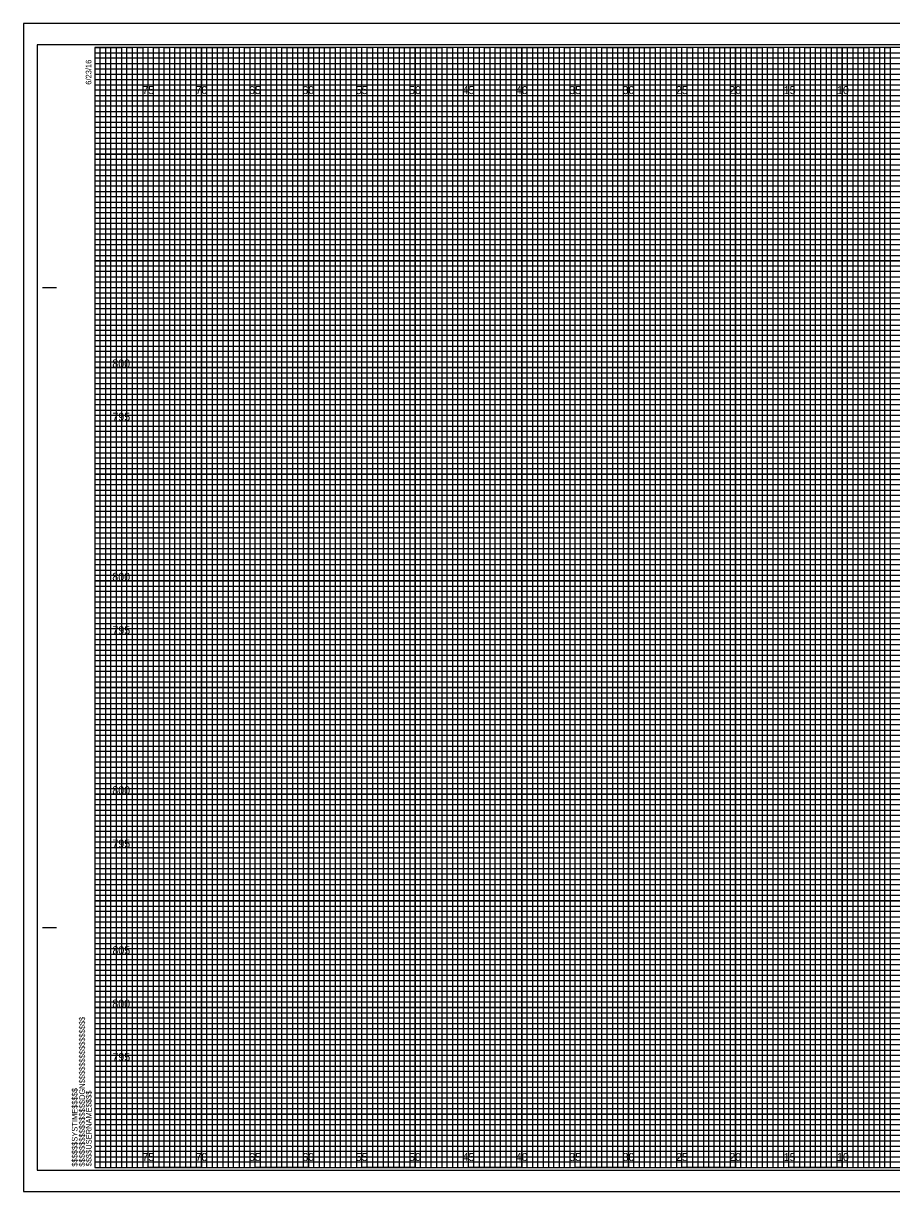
# Model space of a CAD drawing. Extents: x -7 to 162, y -2 to 107.
# Drawn here: x -6.7 to 74.6, y -2.3 to 107.3 of the extents above; entities that cross this region are included whole.
import ezdxf

# ---------------------------------------------------------------- set-up
doc = ezdxf.new("R2010")
doc.units = 0
for name, color, linetype in [('Exist CMT Pavement', 7, 'Continuous'), ('Exist Cross Section Cell', 7, 'Continuous'), ('Exist XS Center Line Elevation Label', 7, 'Continuous'), ('Prop CMT Concrete Structures', 7, 'Continuous'), ('Prop CMT Pvmt Course 2 Wedge', 7, 'Continuous'), ('Prop XS SE Text', 7, 'Continuous'), ('Prop XS Side Slope Text', 7, 'Continuous'), ('Sheet Cross Section Grid Minor 2 CELL', 7, 'Continuous'), ('Sheet DOT Grid CELL', 7, 'Continuous'), ('Sheet Plot Border Inside CELL', 7, 'Continuous'), ('Sheet Plot Border Outside CELL', 7, 'Continuous')]:
    doc.layers.add(name, color=color, linetype=linetype)

msp = doc.modelspace()

# ---------------------------------------------------------------- linework, layer by layer
at = {"layer": 'Exist Cross Section Cell'}
for p, q in [((5, 105), (0, 105)), ((5, 0), (5, 105)), ((15, 105), (10, 105)), ((10, 105), (10, 0)), ((15, 0), (15, 105)), ((25, 105), (20, 105)), ((20, 105), (20, 0)), ((25, 0), (25, 105)), ((35, 105), (30, 105)), ((30, 105), (30, 0)), ((35, 0), (35, 105)), ((45, 105), (40, 105)), ((40, 105), (40, 0)), ((45, 0), (45, 105)), ((55, 105), (50, 105)), ((50, 105), (50, 0)), ((55, 0), (55, 105)), ((65, 105), (60, 105)), ((60, 105), (60, 0)), ((65, 0), (65, 105)), ((75, 105), (70, 105)), ((70, 105), (70, 0)), ((10, 0), (5, 0)), ((20, 0), (15, 0)), ((30, 0), (25, 0)), ((40, 0), (35, 0)), ((50, 0), (45, 0)), ((60, 0), (55, 0)), ((70, 0), (65, 0))]:
    msp.add_line(p, q, dxfattribs=at)
for points in [[(0, 100), (160, 100), (160, 95), (0, 95)], [(0, 90), (160, 90), (160, 85), (0, 85)], [(0, 80), (160, 80), (160, 75), (0, 75)], [(0, 70), (160, 70), (160, 65), (0, 65)], [(0, 60), (160, 60), (160, 55), (0, 55)], [(0, 50), (160, 50), (160, 45), (0, 45)], [(0, 40), (160, 40), (160, 35), (0, 35)], [(0, 30), (160, 30), (160, 25), (0, 25)], [(0, 20), (160, 20), (160, 15), (0, 15)], [(0, 10), (160, 10), (160, 5), (0, 5)]]:
    msp.add_lwpolyline(points, dxfattribs=at)
at = {"layer": 'Exist XS Center Line Elevation Label'}
for points in [[(0, 105), (2.5, 105), (2.5, 0), (7.5, 0), (7.5, 105), (12.5, 105), (12.5, 0), (17.5, 0), (17.5, 105), (22.5, 105), (22.5, 0), (27.5, 0), (27.5, 105), (32.5, 105), (32.5, 0), (37.5, 0), (37.5, 105), (42.5, 105), (42.5, 0), (47.5, 0), (47.5, 105), (52.5, 105), (52.5, 0), (57.5, 0), (57.5, 105), (62.5, 105), (62.5, 0), (67.5, 0), (67.5, 105), (72.5, 105), (72.5, 0), (77.5, 0)], [(0, 102.5), (137.5, 102.5)], [(0, 92.5), (160, 92.5), (160, 97.5), (0, 97.5)], [(0, 82.5), (160, 82.5), (160, 87.5), (0, 87.5)], [(0, 72.5), (160, 72.5), (160, 77.5), (0, 77.5)], [(0, 62.5), (160, 62.5), (160, 67.5), (0, 67.5)], [(0, 52.5), (160, 52.5), (160, 57.5), (0, 57.5)], [(0, 42.5), (160, 42.5), (160, 47.5), (0, 47.5)], [(0, 32.5), (160, 32.5), (160, 37.5), (0, 37.5)], [(0, 22.5), (160, 22.5), (160, 27.5), (0, 27.5)], [(0, 12.5), (160, 12.5), (160, 17.5), (0, 17.5)], [(0, 2.5), (160, 2.5), (160, 7.5), (0, 7.5)]]:
    msp.add_lwpolyline(points, dxfattribs=at)
at = {"layer": 'Prop CMT Concrete Structures'}
for p, q in [((161.65, 107.25), (-6.7, 107.25)), ((-6.7, 107.25), (-6.7, -2.25)), ((-6.7, -2.25), (161.65, -2.25))]:
    msp.add_line(p, q, dxfattribs=at)
at = {"layer": 'Prop CMT Pvmt Course 2 Wedge'}
for p, q in [((-4.9, 82.5), (-3.65, 82.5)), ((-4.85, 82.5), (-3.6, 82.5)), ((-4.9, 22.5), (-3.65, 22.5)), ((-4.85, 22.5), (-3.6, 22.5)), ((0, 0), (0, 0)), ((0, 0), (0, 0)), ((0, 0), (0, 0)), ((0, 0), (0, 0)), ((0, 0), (0, 0)), ((0, 0), (0, 0)), ((0, 0), (0, 0))]:
    msp.add_line(p, q, dxfattribs=at)
msp.add_lwpolyline([(160, 105), (0, 105), (0, 0), (160, 0)], close=True, dxfattribs=at)
at = {"layer": 'Prop XS Side Slope Text'}
for p, q in [((0, 104.5), (130, 104.5)), ((130, 103.99), (0, 103.99)), ((0, 103.99), (0, 103.5)), ((0, 103.5), (130, 103.5)), ((130, 102.95), (0, 102.95)), ((0, 102.95), (0, 102)), ((0, 102), (160, 102))]:
    msp.add_line(p, q, dxfattribs=at)
for points in [[(0, 101.5), (135, 101.5), (160, 101.5), (160, 101), (0, 101)], [(0, 100.5), (160, 100.5), (160, 99.5), (0, 99.5)], [(0, 99), (160, 99), (160, 98.5), (0, 98.49)], [(0, 98), (160, 98), (160, 97), (0, 97)], [(0, 96.5), (160, 96.5), (160, 96), (0, 96)], [(0, 95.5), (160, 95.5), (160, 94.5), (0, 94.5)], [(0, 94), (160, 94), (160, 93.5), (0, 93.5)], [(0, 93), (160, 93), (160, 92), (0, 92)], [(0, 91.5), (160, 91.5), (160, 91), (0, 91)], [(0, 90.5), (160, 90.5), (160, 89.5), (0, 89.5)], [(0, 89), (160, 89), (160, 88.5), (0, 88.5)], [(0, 88), (160, 88), (160, 86.98), (160, 86.5), (160, 86), (0, 86)], [(0, 87), (160, 87), (160, 86.5), (0, 86.5)], [(0, 85.5), (160, 85.5), (160, 84.5), (0, 84.52)], [(0, 84.52), (160, 84.5), (160, 84), (0, 84)], [(0, 83.5), (160, 83.5), (160, 83), (0, 83)], [(0, 82), (160, 82), (160, 81.5), (0, 81.5)], [(0, 81), (160, 81), (160, 80.5), (0, 80.5)], [(-0.04, 79.45), (160, 79.45), (160, 78.94), (-0.04, 78.94)], [(0, 78.5), (160, 78.5), (160, 78), (0, 78)], [(0, 77), (160, 77), (160, 76.5), (0, 76.5)], [(0, 76), (160, 76), (160, 75.5), (0, 75.5)], [(0, 74.5), (160, 74.5), (160, 74), (0, 74)], [(0, 73.5), (160, 73.5), (160, 73), (0, 73)], [(0, 72), (160, 72), (160, 71.5), (0, 71.5)], [(0, 71), (160, 71), (160, 70.5), (0, 70.5)], [(0, 69.5), (160, 69.5), (160, 68.99), (0, 69)], [(0, 68.5), (160, 68.5), (160, 68), (0, 68)], [(0, 67), (160, 67), (160, 66.5), (0, 66.5)], [(0, 66), (160, 66), (160, 65.5), (0, 65.5)], [(0, 64.5), (160, 64.5), (160, 64), (0, 64)], [(0, 63.5), (160, 63.5), (160, 63), (0, 63)], [(0, 62), (160, 62), (160, 61.5), (0, 61.5)], [(0, 61), (160, 61), (160, 60.5), (0, 60.5)], [(0, 59.5), (160, 59.5), (160, 59), (0, 59)], [(0, 58.5), (160.03, 58.45), (160, 58), (0, 58)], [(0, 57), (160, 57), (160, 56.5), (0, 56.5)], [(0, 56), (160, 56), (160, 55.5), (0, 55.5)], [(0, 54.5), (160, 54.5), (160, 54), (0, 54)], [(0, 53.5), (160, 53.5), (160, 53), (0, 53)], [(0, 52), (160, 52), (160, 51.5), (0, 51.5)], [(0, 51), (160, 51), (160, 50.5), (0, 50.5)], [(0, 49.5), (160, 49.5), (160, 49), (0, 49)], [(0, 48.5), (160, 48.5), (160, 48), (0, 48)], [(0, 47), (160, 47), (160, 46.5), (0, 46.5)], [(0, 46), (160, 46), (160, 45.5), (0, 45.5)], [(0, 44.5), (160, 44.5), (160, 44), (0, 44)], [(0, 43.5), (160, 43.5), (160, 43), (0, 43)], [(0, 42), (160, 42), (160, 41.5), (0, 41.5)], [(0, 41), (160, 41), (160, 40.5), (0, 40.5)], [(0, 39.5), (160, 39.5), (160, 38.99), (0, 39)], [(0, 38.5), (160, 38.5), (160, 38), (0, 38)], [(0, 37), (160, 37), (160, 36.5), (0, 36.5)], [(0, 36), (160, 36), (160, 35.5), (0, 35.5)], [(0, 34.5), (160, 34.5), (160, 34), (0, 34)], [(0, 33.5), (160, 33.5), (160, 33), (0, 33)], [(0, 32), (160, 32), (160, 31.5), (0, 31.5)], [(0, 31), (160, 31), (160, 30.5), (0, 30.5)], [(0, 29.5), (160, 29.5), (160, 29), (0, 29)], [(0, 28.5), (160.03, 28.46), (160, 28), (0, 28)], [(0, 27), (160, 27), (160, 26.5), (0, 26.5)], [(0, 26), (160, 26), (160, 25.5), (0, 25.5)], [(0, 24.5), (160, 24.5), (160, 24), (0, 24)], [(0, 23.5), (160, 23.5), (160, 23), (0, 23)], [(0, 22), (160, 22), (160, 21.5), (0, 21.5)], [(0, 21), (160, 21), (160, 20.5), (0, 20.5)], [(0, 19.5), (160, 19.5), (160, 19), (0, 19)], [(0, 18.5), (160, 18.5), (160, 18), (0, 18)], [(0, 17), (160, 17), (160, 16.5), (0, 16.5)], [(0, 16), (160, 16), (160, 15.5), (0, 15.5)], [(0, 14.5), (160, 14.5), (160, 14), (0, 14)], [(0, 13.5), (160, 13.5), (160, 13), (0, 13)], [(0, 12), (160, 12), (160, 11.5), (0, 11.5)], [(0, 11), (160, 11), (160, 10.5), (0, 10.5)], [(0, 9.5), (160, 9.5), (160, 9), (0, 9)], [(0, 8.5), (160, 8.5), (160, 8), (0, 8)], [(0, 7), (160, 7), (160, 6.5), (0, 6.5)], [(0, 6), (160, 6), (160, 5.5), (0, 5.5)], [(0, 4.5), (160, 4.5), (160, 4), (0, 4)], [(0, 3.5), (160, 3.5), (160, 3), (0, 3)], [(0, 2), (160, 2), (160, 1.5), (0, 1.5)], [(0, 1), (160, 1), (160, 0.5), (0, 0.5)]]:
    msp.add_lwpolyline(points, dxfattribs=at)
at = {"layer": 'Sheet Cross Section Grid Minor 2 CELL'}
for points in [[(0, 0), (0.5, 0), (0.5, 105), (1, 105), (1, 0)], [(1, 0), (1.5, 0), (1.5, 105), (2, 105), (2, 0)], [(2.5, 0), (3, 0), (3, 105), (3.5, 105), (3.5, 0)], [(3.5, 0), (4, 0), (4, 105), (4.5, 105), (4.5, 0)], [(5, 0), (5.5, 0), (5.5, 105), (6, 105), (6, 0)], [(6, 0), (6.5, 0), (6.5, 105), (7, 105), (7, 0)], [(7.5, 0), (8, 0), (8, 105), (8.5, 105), (8.5, 0)], [(8.5, 0), (9, 0), (9, 105), (9.5, 105), (9.5, 0)], [(10, 0), (10.5, 0), (10.5, 105), (11, 105), (11, 0)], [(11, 0), (11.5, 0), (11.5, 105), (12, 105), (12, 0)], [(12.5, 0), (13, 0), (13, 105), (13.5, 105), (13.5, 0)], [(13.5, 0), (14, 0), (14, 105), (14.5, 105), (14.5, 0)], [(15, 0), (15.5, 0), (15.5, 105), (16, 105), (16, 0)], [(16, 0), (16.5, 0), (16.5, 105), (17, 105), (17, 0)], [(17.5, 0), (18, 0), (18, 105), (18.5, 105), (18.5, 0)], [(18.5, 0), (19, 0), (19, 105), (19.5, 105), (19.5, 0)], [(20, 0), (20.5, 0), (20.5, 105), (21, 105), (21, 0)], [(21, 0), (21.5, 0), (21.5, 105), (22, 105), (22, 0)], [(22.5, 0), (23, 0), (23, 105), (23.5, 105), (23.5, 0)], [(23.5, 0), (24, 0), (24, 105), (24.5, 105), (24.5, 0)], [(25, 0), (25.5, 0), (25.5, 105), (26, 105), (26, 0)], [(26, 0), (26.5, 0), (26.5, 105), (27, 105), (27, 0)], [(27.5, 0), (28, 0), (28, 105), (28.5, 105), (28.5, 0)], [(28.5, 0), (29, 0), (29, 105), (29.5, 105), (29.5, 0)], [(30, 0), (30.5, 0), (30.5, 105), (31, 105), (31, 0)], [(31, 0), (31.5, 0), (31.5, 105), (32, 105), (32, 0)], [(32.5, 0), (33, 0), (33, 105), (33.5, 105), (33.5, 0)], [(33.5, 0), (34, 0), (34, 105), (34.5, 105), (34.5, 0)], [(35, 0), (35.5, 0), (35.5, 105), (36, 105), (36, 0)], [(36, 0), (36.5, 0), (36.5, 105), (37, 105), (37, 0)], [(37.5, 0), (38, 0), (38, 105), (38.5, 105), (38.5, 0)], [(38.5, 0), (39, 0), (39, 105), (39.5, 105), (39.5, 0)], [(40, 0), (40.5, 0), (40.5, 105), (41, 105), (41, 0)], [(41, 0), (41.5, 0), (41.5, 105), (42, 105), (42, 0)], [(42.5, 0), (43, 0), (43, 105), (43.5, 105), (43.5, 0)], [(43.5, 0), (44, 0), (44, 105), (44.5, 105), (44.5, 0)], [(45, 0), (45.5, 0), (45.5, 105), (46, 105), (46, 0)], [(46, 0), (46.5, 0), (46.5, 105), (47, 105), (47, 0)], [(47.5, 0), (48, 0), (48, 105), (48.5, 105), (48.5, 0)], [(48.5, 0), (49, 0), (49, 105), (49.5, 105), (49.5, 0)], [(50, 0), (50.5, 0), (50.5, 105), (51, 105), (51, 0)], [(51, 0), (51.5, 0), (51.5, 105), (52, 105), (52, 0)], [(52.5, 0), (53, 0), (53, 105), (53.5, 105), (53.5, 0)], [(53.5, 0), (54, 0), (54, 105), (54.5, 105), (54.5, 0)], [(55, 0), (55.5, 0), (55.5, 105), (56, 105), (56, 0)], [(56, 0), (56.5, 0), (56.5, 105), (57, 105), (57, 0)], [(57.5, 0), (58, 0), (58, 105), (58.5, 105), (58.5, 0)], [(58.5, 0), (59, 0), (59, 105), (59.5, 105), (59.5, 0)], [(60, 0), (60.5, 0), (60.5, 105), (61, 105), (61, 0)], [(61, 0), (61.5, 0), (61.5, 105), (62, 105), (62, 0)], [(62.5, 0), (63, 0), (63, 105), (63.5, 105), (63.5, 0)], [(63.5, 0), (64, 0), (64, 105), (64.5, 105), (64.5, 0)], [(65, 0), (65.5, 0), (65.5, 105), (66, 105), (66, 0)], [(66, 0), (66.5, 0), (66.5, 105), (67, 105), (67, 0)], [(67.5, 0), (68, 0), (68, 105), (68.5, 105), (68.5, 0)], [(68.5, 0), (69, 0), (69, 105), (69.5, 105), (69.5, 0)], [(70, 0), (70.5, 0), (70.5, 105), (71, 105), (71, 0)], [(71, 0), (71.5, 0), (71.5, 105), (72, 105), (72, 0)], [(72.5, 0), (73, 0), (73, 105), (73.5, 105), (73.5, 0)], [(73.5, 0), (74, 0), (74, 105), (74.5, 105), (74.5, 0)]]:
    msp.add_lwpolyline(points, dxfattribs=at)
at = {"layer": 'Sheet DOT Grid CELL'}
for p, q in [((5, 0), (5, 105)), ((10, 0), (10, 105)), ((15, 0), (15, 105)), ((20, 0), (20, 105)), ((25, 0), (25, 105)), ((30, 0), (30, 105)), ((35, 0), (35, 105)), ((40, 0), (40, 105)), ((45, 0), (45, 105)), ((50, 0), (50, 105)), ((55, 0), (55, 105)), ((60, 0), (60, 105)), ((65, 0), (65, 105)), ((70, 0), (70, 105)), ((0, 100), (160, 100)), ((0, 95), (160, 95)), ((0, 90), (160, 90)), ((0, 85), (160, 85)), ((0, 80), (160, 80)), ((0, 75), (160, 75)), ((0, 70), (160, 70)), ((0, 65), (160, 65)), ((0, 60), (160, 60)), ((0, 55), (160, 55)), ((0, 50), (160, 50)), ((0, 45), (160, 45)), ((0, 40), (160, 40)), ((0, 35), (160, 35)), ((0, 30), (160, 30)), ((0, 25), (160, 25)), ((0, 20), (160, 20)), ((0, 15), (160, 15)), ((0, 10), (160, 10)), ((0, 5), (160, 5))]:
    msp.add_line(p, q, dxfattribs=at)
at = {"layer": 'Sheet Plot Border Inside CELL'}
msp.add_lwpolyline([(-5.4, -0.25), (161.2, -0.25), (161.2, 105.25), (-5.4, 105.25)], close=True, dxfattribs=at)
at = {"layer": 'Sheet Plot Border Outside CELL'}
msp.add_lwpolyline([(-6.7, -2.25), (161.65, -2.25), (161.65, 107.25), (-6.7, 107.25)], close=True, dxfattribs=at)

# ---------------------------------------------------------------- texts
at = {"layer": 'Exist CMT Pavement'}
for s, p in [('800', (1.63, 75)), ('795', (1.64, 70)), ('800', (1.63, 55)), ('795', (1.64, 50)), ('800', (1.63, 35)), ('795', (1.64, 30)), ('805', (1.64, 20)), ('800', (1.63, 15)), ('795', (1.64, 10))]:
    msp.add_text(s, height=0.75, dxfattribs=at).set_placement(p)
at = {"layer": 'Prop CMT Pvmt Course 2 Wedge'}
for s, p in [('6/23/16', (-0.33, 101.5)), ('$$$$$$$$$$$$$$$$DGN$$$$$$$$$$$$$$$$', (-0.94, 0.09)), ('$$$$$$SYSTIME$$$$$', (-1.63, 0.09)), ('$$$$USERNAME$$$$', (-0.31, 0.12))]:
    msp.add_text(s, height=0.525, rotation=90, dxfattribs=at).set_placement(p)
at = {"layer": 'Prop XS SE Text'}
for s, p in [('75', (4.44, 100.62)), ('70', (9.43, 100.62)), ('65', (14.44, 100.62)), ('60', (19.43, 100.62)), ('55', (24.44, 100.62)), ('50', (29.43, 100.62)), ('45', (34.44, 100.62)), ('40', (39.43, 100.62)), ('35', (44.44, 100.62)), ('30', (49.43, 100.62)), ('25', (54.44, 100.62)), ('20', (59.43, 100.62)), ('15', (64.53, 100.62)), ('10', (69.52, 100.62)), ('75', (4.44, 0.62)), ('70', (9.43, 0.62)), ('65', (14.44, 0.62)), ('60', (19.43, 0.62)), ('55', (24.44, 0.62)), ('50', (29.43, 0.62)), ('45', (34.44, 0.62)), ('40', (39.43, 0.62)), ('35', (44.44, 0.62)), ('30', (49.43, 0.62)), ('25', (54.44, 0.62)), ('20', (59.43, 0.62)), ('15', (64.53, 0.62)), ('10', (69.52, 0.62))]:
    msp.add_text(s, height=0.75, dxfattribs=at).set_placement(p)

doc.saveas('drawing.dxf')
